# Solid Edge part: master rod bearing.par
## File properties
Author: Robert a Rhodes jr
Template: Normal.par
Last saved by: CADCIM
Revision: 4
Application: Solid Edge
Accuracy: 0.99
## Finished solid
Body 1: solid body, 4 faces, 4 edges, 0 vertices.
  Faces by surface: cylinder 2, plane 2
  Edges by curve: circle 4
Bounding box of the edges (mm): 52.000 x 52.000 x 70.000, from (-26, -26, -70) to (26, 26, 0).
Cylindrical faces by radius (mm): R23 x1, R26 x1
Planar faces by outward normal: +z 1, -z 1
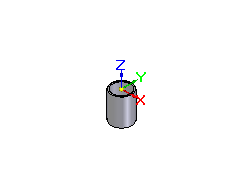
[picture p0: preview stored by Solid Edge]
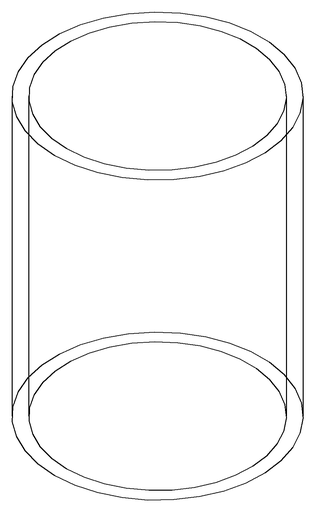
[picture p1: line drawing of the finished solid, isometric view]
